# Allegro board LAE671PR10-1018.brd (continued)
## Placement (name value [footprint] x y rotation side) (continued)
PQ129  -  [DMN66D0LDW-7_SOT363-6]  52.66 18.61 90 bottom
PQ133  S TR AO7401 1P SC70-3  [SI1303DL-T1-E3_SOT323-3]  33.12 17.61 0 bottom
PQ134  -  [DMN66D0LDW-7_SOT363-6]  33.84 12.81 180 bottom
PQ135  S TR AO7401 1P SC70-3  [SI1303DL-T1-E3_SOT323-3]  46.81 19.43 0 bottom
PQ136  -  [DMN66D0LDW-7_SOT363-6]  49.28 19.35 0 bottom
PQ149  -  [DMN66D0LDW-7_SOT363-6]  177.45 11.8 90 bottom
PQ150  S TR AO7401 1P SC70-3  [SI1303DL-T1-E3_SOT323-3]  181.52 10.71 0 bottom
PQ151  -  [DMN66D0LDW-7_SOT363-6]  215.7 4.01 270 bottom
PQ153  -  [AON7405_DFN8-5]  193.28 7.72 270 bottom
PQ155  -  [AON7405_DFN8-5]  185.68 5.72 90 bottom
PQ156  -  [L2N7002WT1G_SC70-3]  191.68 3.86 0 bottom
PQ157  -  [L2N7002WT1G_SC70-3]  184.69 9.81 90 bottom
PQ158  S TR AO7401 1P SC70-3  [SI1303DL-T1-E3_SOT323-3]  196.1 3.67 0 bottom
PQ199  -  [L2N7002WT1G_SC70-3]  26.13 24.81 270 bottom
PQ200  -  [L2N7002WT1G_SC70-3]  33.81 32.42 270 bottom
PQ201  -  [L2N7002WT1G_SC70-3]  212.74 14.17 90 bottom
PQ300  -  [L2N7002WT1G_SC70-3]  61.13 13.72 180 bottom
PQ302  -  [AON6992_DFN5X6D-8-7]  62.5 20.91 180 bottom
PQ304  -  [AON7405_DFN8-5]  83.22 12.63 90 bottom
PQ307  -  [AON6992_DFN5X6D-8-7]  75.02 20.95 270 bottom
PR100  499K_0402_1%  [R_0402]  34.41 17.86 180 top
PR101  300K_0402_1%  [R_0402]  36.31 9.25 180 bottom
PR102  1M_0603_1%  [R_0603]  84.57 9.09 180 bottom
PR103  499K_0402_1%  [R_0402]  39.87 6.69 180 top
PR106  49.9K_0402_1%  [R_0402]  33.19 18.93 90 top
PR107  100K_0402_1%  [R_0402]  36.87 5.04 0 top
PR108  0_0402_5%  [R0402_0OHM]  22.26 26.08 0 bottom
PR109  49.9K_0402_1%  [R_0402]  34.3 10.1 270 bottom
PR110  100K_0201_1%  [R_0201]  23.17 25.33 180 bottom
PR111  0_0402_5%  [R0402_0OHM]  23.18 24.58 180 bottom
PR112  100K_0201_1%  [R_0201]  27.21 24.6 0 bottom
PR114  0_0402_5%  [R0402_0OHM]  31.17 8.17 270 top
PR115  200K_0402_1%  [R_0402]  41.19 4.15 90 top
PR117  0_0402_5%  [R0402_0OHM]  29.79 31.52 0 bottom
PR118  100K_0402_1%  [R_0402]  46.65 6.26 270 top
PR119  100K_0201_1%  [R_0201]  31.45 30.82 270 bottom
PR120  0_0402_5%  [R0402_0OHM]  33.06 30.69 180 bottom
PR121  100K_0201_1%  [R_0201]  30.82 32.86 270 bottom
PR122  0_0402_5%  [R0402_0OHM]  31.21 21.04 0 top
PR123  0_0402_5%  [R0402_0OHM]  37.23 7.45 270 top
PR124  200K_0402_1%  [R_0402]  54.4 14.94 180 top
PR126  0_0402_5%  [R0402_0OHM]  216.69 13.46 180 bottom
PR127  200K_0402_1%  [R_0402]  60.5 9.94 270 bottom
PR128  499K_0402_1%  [R_0402]  43.93 18.88 270 top
PR129  300K_0402_1%  [R_0402]  50.99 8.57 270 top
PR130  499K_0402_1%  [R_0402]  46.01 8.72 270 top
PR132  0_0402_5%  [R0402_0OHM]  49.21 16.16 0 top
PR133  49.9K_0402_1%  [R_0402]  43.92 17.12 0 top
PR134  49.9K_0402_1%  [R_0402]  45.76 6.43 270 top
PR135  0_0402_5%  [R0402_0OHM]  42.97 5.16 270 top
PR136  0_0402_5%  [R0402_0OHM]  48.71 5.29 90 top
PR137  0_0402_5%  [R0402_0OHM]  213.11 15.91 0 bottom
PR138  0_0402_5%  [R0402_0OHM]  51.68 15.86 0 top
PR139  200K_0402_1%  [R_0402]  44.74 2.39 90 top
PR140  100K_0201_1%  [R_0201]  215.99 14.2 0 bottom
PR141  100K_0201_1%  [R_0201]  211.74 14.05 180 bottom
PR142  200K_0402_1%  [R_0402]  54.4 15.86 180 top
PR143  200K_0402_1%  [R_0402]  61.41 9.99 0 bottom
PR144  0_0402_5%  [R0402_0OHM]  49.6 5.29 90 top
PR145  0_0402_5%  [R0402_0OHM]  43.85 4.91 0 top
PR148  1M_0402_1%  [R_0402]  47.11 3.31 270 top
PR149  300K_0402_5%  [R_0402]  38.01 1.99 0 top
PR150  10K_0402_1%  [R_0402]  50.97 3.08 270 top
PR151  0_0402_5%  [R0402_0OHM]  51.98 3.59 270 top
PR152  100_0402_1%  [R_0402]  97.63 13.89 270 top
PR153  300K_0402_5%  [R_0402]  38.9 3.26 180 top
PR154  100_0402_1%  [R_0402]  99.52 13.89 270 top
PR155  100K_0402_1%  [R_0402]  49.14 1.99 180 top
PR156  0_0402_5%  [R0402_0OHM]  49.14 2.88 180 top
PR157  100_0402_1%  [R_0402]  100.43 13.9 270 top
PR158  100K_0402_1%  [R_0402]  59.09 6.26 0 top
PR166  1M_0402_1%  [R_0402]  32.25 19.26 180 top
PR170  0_0402_5%  [R0402_0OHM]  63.21 9.1 90 bottom
PR171  200K_0402_1%  [R_0402]  68.57 9.96 270 bottom
PR172  1M_0402_1%  [R_0402]  49.19 14.38 0 top
PR173  200K_0402_1%  [R_0402]  67.65 9.99 270 bottom
PR174  200K_0402_1%  [R_0402]  51.55 19.7 270 bottom
PR175  200K_0402_1%  [R_0402]  52.69 20.35 0 top
PR176  1M_0402_1%  [R_0402]  38.11 6.53 90 top
PR177  1M_0402_1%  [R_0402]  47.82 5.29 90 top
PR178  1M_0402_1%  [R_0402]  32.04 8.54 90 top
PR179  1M_0402_1%  [R_0402]  42.08 4.27 90 top
PR192  0_0402_5%  [R0402_0OHM]  53.61 16.77 180 top
PR195  0_0402_5%  [R0402_0OHM]  64.99 9.99 270 bottom
PR196  0_0402_5%  [R0402_0OHM]  66.79 9.99 180 bottom
PR200  0_0402_5%  [R0402_0OHM]  64.1 9.07 90 bottom
PR201  0_0402_5%  [R0402_0OHM]  51.7 14.08 0 top
PR202  0_0402_5%  [R0402_0OHM]  52.69 17.66 0 top
PR203  0_0402_5%  [R_0402]  51.7 14.97 0 top
PR204  0_0402_5%  [R_0402]  61.41 9.07 0 bottom
PR205  0_0402_5%  [R_0402]  65.88 9.07 0 bottom
PR206  0_0402_5%  [R0402_0OHM]  54.47 16.77 90 top
PR207  0_0402_5%  [R0402_0OHM]  54.47 18.55 90 top
PR208  0_0402_5%  [R0402_0OHM]  53.61 19.44 180 top
PR209  0_0402_5%  [R0402_0OHM]  51.7 19.44 270 top
PR213  300K_0402_1%  [R_0402]  32.6 14.61 90 top
PR214  300K_0402_1%  [R_0402]  33.49 15.53 270 top
PR215  200K_0402_1%  [R_0402]  30.86 11.79 90 bottom
PR217  0_0402_5%  [R0402_0OHM]  31.66 18.07 270 top
PR218  1M_0402_1%  [R_0402]  39.54 20.17 90 top
PR219  1M_0402_1%  [R_0402]  42.16 18.89 270 top
PR220  300K_0402_1%  [R_0402]  44.82 18.9 270 top
PR221  300K_0402_1%  [R_0402]  45.7 18.22 270 top
PR222  200K_0402_1%  [R_0402]  49.27 19.26 0 top
PR224  0_0402_5%  [R0402_0OHM]  49.29 18.36 0 top
PR228  1M_0402_1%  [R_0402]  32.55 17.15 90 top
PR229  1M_0402_1%  [R_0402]  50.2 17.48 180 top
PR230  0_0402_5%  [R0402_0OHM]  53.61 18.57 180 top
PR259  0_0402_5%  [R0402_0OHM]  216.69 2.89 270 bottom
PR260  49.9K_0402_1%  [R_0402]  194.3 4.46 180 bottom
PR261  499K_0402_1%  [R_0402]  184.29 6.97 90 bottom
PR262  300K_0402_1%  [R_0402]  198.01 2.71 270 bottom
PR263  499K_0402_1%  [R_0402]  195.52 6.23 270 bottom
PR264  300K_0402_1%  [R_0402]  196.39 6.23 270 bottom
PR266  1M_0402_1%  [R_0402]  214.59 1.72 0 bottom
PR267  0_0402_5%  [R0402_0OHM]  184.37 10.83 180 bottom
PR268  300K_0402_1%  [R_0402]  182.46 6.97 90 bottom
PR269  1M_0402_1%  [R_0402]  193.05 9.16 180 bottom
PR270  200K_0402_1%  [R_0402]  179.01 14.13 180 bottom
PR271  0_0402_5%  [R0402_0OHM]  194.3 1.81 180 bottom
PR272  1M_0402_1%  [R_0402]  180.3 11.94 90 bottom
PR273  100K_0402_1%  [R_0402]  179.67 9.4 90 bottom
PR274  49.9K_0402_1%  [R_0402]  183.43 8.77 0 bottom
PR275  1M_0402_1%  [R_0402]  193.39 3.58 0 bottom
PR276  200K_0402_1%  [R_0402]  216.68 4.68 270 bottom
PR277  1M_0402_1%  [R_0402]  187.7 8.97 90 bottom
PR278  0_0402_5%  [R0402_0OHM]  181.19 12.86 270 bottom
PR300  0.02_1206_1%  [R_1206_4P-D]  54.44 11.75 0 bottom
PR301  3.3_0402_1%  [R_0402]  63.79 18.75 270 top
PR302  3.3_0402_1%  [R_0402]  62.4 18.75 270 top
PR303  2_1206_5%  [R_1206]  56.05 17.15 0 top
PR304  .01_2512_1%  [R_2512]  74.93 13.51 0 bottom
PR305  442K_0402_1%  [R_0402]  58.12 10.87 90 top
PR306  2.2_0603_5%  [R_0603]  64.98 17.98 270 top
PR307  100K_0402_1%  [R_0402]  59.03 12.61 270 top
PR308  4.7_0402_5%  [R_0402]  67.21 16.24 90 top
PR309  2_1206_5%  [R_1206]  56.55 12.15 90 top
PR311  2.2_0603_5%  [R_0603]  69.36 13.41 270 bottom
PR313  0_0402_5%  [R0402_0OHM]  59.12 9.88 0 top
PR314  0_0402_5%  [R0402_0OHM]  59.09 8.96 0 top
PR315  75_0402_5%  [R_0402]  59.09 8.01 0 top
PR316  4.7_1206_5%  [R_1206]  65.81 26.26 180 top
PR317  4.7_1206_5%  [R_1206]  70.66 23.97 180 top
PR318  0_0402_5%  [R0402_0OHM]  70.02 8.97 0 bottom
PR319  100K_0402_1%  [R_0402]  60.73 12.39 0 bottom
PR320  154K_0402_1%  [R_0402]  60.74 11.49 0 bottom
PR321  0_0402_5%  [R0402_0OHM]  58.22 3.3 270 bottom
PR322  93.1K_0402_1%  [R_0402]  63.28 8.07 270 top
PR323  2.2_0402_1%  [R_0402]  70.14 10.2 180 top
PR324  2.2_0402_1%  [R_0402]  70.14 9.31 180 top
PR325  100K_0402_1%  [R_0402]  59.09 7.12 0 top
PR326  1M_0402_1%  [R_0402]  61.48 6.25 0 top
PR327  499_0402_1%  [R_0402]  65.09 8.06 270 top
PR328  1K_0402_1%  [R_0402]  15.36 4.15 180 top
PR329  0_0402_5%  [R0402_0OHM]  67.47 6.25 270 top
PR330  100_0402_1%  [R_0402]  69.24 7.52 0 top
PR331  100K_0402_1%  [R_0402]  63.18 2.37 180 bottom
PR332  0_0402_5%  [R0402_0OHM]  62.4 7.15 90 top
PR333  10K_0402_5%  [R_0402]  68.36 5.33 90 top
PR334  0_0402_5%  [R0402_0OHM]  59.06 10.81 0 top
PR335  1M_0402_1%  [R_0402]  61.71 3.37 0 bottom
PR336  100K_0402_1%  [R_0402]  60.49 2.45 0 bottom
PR340  1M_0402_1%  [R_0402]  60.86 16.8 0 bottom
PR341  0_0402_5%  [R0402_0OHM]  14.44 5.93 0 top
PR342  0_0402_5%  [R0402_0OHM]  29.07 19.46 270 bottom
PR343  0_0402_5%  [R0402_0OHM]  58.22 4.13 90 bottom
PR344  0_0402_5%  [R0402_0OHM]  68.53 6.7 270 bottom
PR345  0_0402_5%  [R0402_0OHM]  68.37 2.08 90 bottom
PR346  0_0402_5%  [R0402_0OHM]  68.37 4.73 270 bottom
PR500  0_0402_5%  [R_0402]  53.87 27.98 0 bottom
PR501  4.7_1206_5%  [R_1206]  52.5 31.73 180 top
PR502  100K_0402_5%  [R_0402]  47.77 27.7 180 bottom
PR503  0_0402_5%  [R0402_0OHM]  46.85 25.04 0 bottom
PR504  1K_0402_5%  [R_0402]  46.85 26.81 0 bottom
PR505  0_0402_5%  [R_0402]  42.18 27.32 90 top
PR506  0_0402_5%  [R_0402]  38.66 22.46 0 bottom
PR507  4.7_1206_5%  [R_1206]  41.71 31.33 180 top
PR508  499K_0402_1%  [R_0402]  36.87 23.18 90 bottom
PR509  499K_0402_1%  [R_0402]  35.99 23.91 270 bottom
PR510  0_0402_5%  [R0402_0OHM]  35.96 24.98 0 bottom
PR511  1K_0402_5%  [R_0402]  35.96 26.84 0 bottom
PR512  0_0603_5%  [R0603_0OHM]  38.9 33.48 0 top
PR600  100K_0402_5%  [R_0402]  113.45 3.74 180 bottom
PR601  100K_0402_5%  [R_0402]  113.45 2.72 180 bottom
PR602  4.7_0603_5%  [R_0603]  124.68 2.75 0 bottom
PR603  100K_0402_1%  [R_0402]  116.3 2.35 90 bottom
PR604  0_0402_5%  [R_0402]  115.19 1.74 180 bottom
PR605  100K_0402_1%  [R_0402]  118.06 3.29 270 bottom
PR606  0_0402_5%  [R0402_0OHM]  114.27 2.74 0 bottom
PR607  0_0402_5%  [R0402_0OHM]  113.48 9.93 270 bottom
PR608  1M_0402_1%  [R_0402]  114.36 9.03 90 bottom
PR609  0_0402_5%  [R0402_0OHM]  113.47 10.84 0 bottom
PR610  1M_0402_1%  [R_0402]  115.26 10.8 90 bottom
PR611  0_0402_5%  [R_0402]  117.93 11.67 180 bottom
PR612  0_0603_5%  [R_0603]  122.34 2.75 0 bottom
PR700  4.7_1206_5%  [R_1206]  140.57 4.66 180 top
PR701  0_0402_5%  [R_0402]  135.79 2.41 0 bottom
PR702  14K_0402_1%  [R_0402]  136.85 11.41 180 bottom
PR703  0_0402_5%  [R0402_0OHM]  131.78 9.24 180 bottom
PR704  1M_0402_1%  [R_0402]  131.76 8.37 270 bottom
PR705  20K_0402_1%  [R_0402]  134.68 8.69 90 bottom
PR706  0_0402_5%  [R_0402]  132.88 9.62 270 bottom
PR707  0_0402_5%  [R0402_0OHM]  133.77 8.7 90 bottom
PR800  0_0402_5%  [R_0402]  163.92 59.12 180 bottom
PR801  0_0402_5%  [R0402_0OHM]  163.91 60 180 bottom
PR802  412K_0402_1%  [R_0402]  154.9 64.18 0 bottom
PR803  4.7_0603_5%  [R_0603]  153.33 62 270 bottom
PR804  324K_0402_1%  [R_0402]  156.76 64.17 270 bottom
PR805  100K_0402_5%  [R_0402]  153.91 64.09 180 bottom
PR806  0_0402_5%  [R0402_0OHM]  160.73 65.02 180 bottom
PR900  0_0402_5%  [R0402_0OHM]  152.03 4.37 270 bottom
PR901  0_0402_5%  [R_0402]  152.06 6.13 270 bottom
PR902  412K_0402_1%  [R_0402]  160.79 8.2 180 bottom
PR903  4.7_0805_5%  [R_0805]  156.76 12.4 90 bottom
PR904  324K_0402_1%  [R_0402]  159.87 6.44 0 bottom
PR905  100K_0402_5%  [R_0402]  158.29 8.83 90 bottom
PR906  0_0402_5%  [R0402_0OHM]  159.86 5.06 0 bottom
PR1000  8.25K_0402_1%  [R_0402]  35.52 42.04 90 top
PR1001  1_0402_5%  [R_0402]  35.3 48.72 0 bottom
PR1002  0_0402_5%  [R0402_0OHM]  38.27 49.69 180 bottom
PR1003  45.3_0402_1%  [R_0402]  33.56 46.08 0 top
PR1004  100_0402_1%  [R_0402]  33.57 47.71 0 top
PR1005  10_0402_1%  [R_0402]  35.31 47.84 0 top
PR1006  93.1K_0402_1%  [R_0402]  37.4 42.04 90 bottom
PR1007  0_0402_5%  [R0402_0OHM]  35.31 46.96 0 top
PR1008  49.9_0402_1%  [R_0402]  35.32 46.08 0 top
PR1009  100_0402_1%  [R_0402]  37.72 47.46 270 bottom
PR1010  27.4K_0402_1%  [R_0402]  37.4 41.21 0 top
PR1011  10.2K_0402_1%  [R_0402]  38.29 42.06 90 top
PR1012  1.91K_0402_1%  [R_0402]  35.32 44.3 0 top
PR1013  165K_0402_1%  [R_0402]  37.04 52.82 90 top
PR1014  34K_0402_1%  [R_0402]  36.19 52.65 180 top
PR1015  150K_0402_1%  [R_0402]  36.19 51.76 180 top
PR1016  110K_0402_1%  [R_0402]  36.19 50.87 180 top
PR1017  0_0402_5%  [R0402_0OHM]  35.32 45.19 0 top
PR1018  3.6K_0402_1%  [R_0402]  39.21 42.04 90 bottom
PR1019  2K_0402_1%  [R_0402]  40.98 40.29 90 top
PR1020  0_0402_5%  [R0402_0OHM]  34.56 42.07 90 top
PR1021  665_0402_1%  [R_0402]  39.68 52.83 90 top
PR1022  1K_0402_1%  [R_0402]  40.1 40.29 90 top
PR1023  34K_0402_1%  [R_0402]  37.95 52.81 90 top
PR1024  1K_0402_1%  [R_0402]  38.83 54.57 90 top
PR1025  11K_0402_1%  [R_0402]  36.16 54.57 90 top
PR1026  2.61K_0402_1%  [R_0402]  38.8 57.26 270 top
PR1027  1.91K_0402_1%  [R_0402]  39.2 40.25 90 top
PR1028  316_0402_1%  [R_0402]  42.64 55.53 270 top
PR1029  1.69K_0402_1%  [R_0402]  41.77 53.75 270 top
PR1030  2.61K_0402_1%  [R_0402]  42.13 42.98 270 bottom
PR1031  1K_0402_1%  [R_0402]  43.91 42.12 180 bottom
PR1032  2.43K_0402_1%  [R_0402]  44.59 54.69 0 top
PR1033  2K_0402_1%  [R_0402]  41.78 54.63 180 top
PR1034  11K_0402_1%  [R_0402]  40.4 42.96 270 bottom
PR1035  115K_0402_1%  [R_0402]  44.62 52.89 90 top
PR1036  360_0402_1%  [R_0402]  42.13 42.07 90 top
PR1037  383_0402_1%  [R_0402]  46.08 49.53 0 bottom
PR1038  11K_0402_1%  [R_0402]  48.8 48.93 0 bottom
PR1039  1K_0402_1%  [R_0402]  47.89 50.4 270 bottom
PR1040  5.49K_0402_1%  [R_0402]  48.78 50.76 0 bottom
PR1041  10.2K_0402_1%  [R_0402]  48.38 44.81 180 bottom
PR1042  316_0402_1%  [R_0402]  46.06 48.44 0 bottom
PR1043  100K_0402_1%  [R_0402]  46.43 44.81 270 bottom
PR1044  27.4K_0402_1%  [R_0402]  48.38 43.94 180 bottom
PR1045  2K_0402_1%  [R_0402]  46.05 47.55 0 top
PR1046  1.54K_0402_1%  [R_0402]  46.06 47.56 0 bottom
PR1047  2.26K_0402_1%  [R_0402]  48.68 45.93 0 bottom
PR1048  0_0402_5%  [R_0402]  44.77 42.96 270 bottom
PR1049  0_0402_5%  [R0402_0OHM]  45.53 52.89 90 top
PR1050  0_0402_5%  [R_0402]  46.52 52.89 90 top
PR1100  0_0402_5%  [R_0402]  61.54 60.49 270 bottom
PR1101  10_1206_5%  [R_1206]  70.41 60.22 90 top
PR1102  0_0402_5%  [R_0402]  61.18 49.33 0 top
PR1103  0_0402_5%  [R_0402]  61.19 48.44 0 top
PR1104  100K_0402_1%  [R_0402]  48.79 50.36 270 top
PR1105  3.65K_0603_1%  [R_0603]  49.82 49.6 90 top
PR1106  2.2_0402_1%  [R_0402]  48.73 51.57 180 top
PR1107  100K_0402_1%  [R_0402]  50.61 52.36 180 top
PR1108  0_0402_5%  [R_0402]  61.16 50.63 0 top
PR1109  0_0402_5%  [R_0402]  61.23 50.83 0 bottom
PR1110  10_1206_5%  [R_1206]  68.72 49.38 90 top
PR1111  0_0402_5%  [R_0402]  61.15 51.54 0 top
PR1112  3.65K_0603_1%  [R_0603]  41.61 44.28 180 bottom
PR1113  100K_0402_1%  [R_0402]  48.35 52.92 180 top
PR1114  3.65K_0603_1%  [R_0603]  49.44 53.45 0 top
PR1115  2.2_0402_1%  [R_0402]  46.96 51.6 180 top
PR1116  100K_0402_1%  [R_0402]  47.88 50.38 270 top
PR1117  100K_0402_1%  [R_0402]  42.61 44.33 0 bottom
PR1118  2.2_0402_1%  [R_0402]  46.87 42.02 90 bottom
PR1119  100K_0402_1%  [R_0402]  45.85 42.02 90 bottom
PR1150  0_0402_5%  [R_0402]  62.87 42.59 270 bottom
PR1151  4.7_1206_5%  [R_1206]  72.35 42.48 270 top
PR1152  3.65K_0603_1%  [R_0603]  51.35 42.18 270 top
PR1153  100K_0402_1%  [R_0402]  45.65 42.04 90 top
PR1154  2.2_0402_1%  [R_0402]  44.52 41.1 180 top
PR1155  100K_0402_1%  [R_0402]  44.76 42.05 90 top
PR1156  2.2_0603_1%  [R_0603]  54.59 45.04 180 bottom
PR1157  4.7_1206_5%  [R_1206]  54.61 56.82 270 top
PR1158  3.65K_0603_1%  [R_0603]  41.19 56.73 180 top
PR1159  0_0402_5%  [R0402_0OHM]  35.22 55.53 270 top
PR1400  0_0402_5%  [R0402_0OHM]  163.17 50.99 90 bottom
PR1401  0_0402_5%  [R0402_0OHM]  164.97 50.11 180 bottom
PR1402  0_0402_5%  [R_0402]  164.06 51.02 0 bottom
PR1403  4.7_0603_5%  [R_0603]  156.57 54.69 180 bottom
PR1404  10K_0402_1%  [R_0402]  166.57 58.25 180 bottom
PR1405  10K_0402_1%  [R_0402]  167.5 57.38 180 bottom
PR1406  10K_0402_1%  [R_0402]  165.65 59.15 0 bottom
PR1407  10K_0402_1%  [R_0402]  165.72 56.46 90 bottom
PR1408  100_0402_1%  [R_0402]  160.82 58.25 0 bottom
PR1409  0_0402_5%  [R0402_0OHM]  162.6 58.25 0 bottom
PR1411  0_0402_5%  [R_0402]  158.53 66.02 90 bottom
PR1412  130K_0402_1%  [R_0402]  162.56 66.03 90 bottom
PR1413  0_0402_5%  [R_0402]  161.67 66.95 270 bottom
PR1414  10K_0402_1%  [R_0402]  161.91 74.03 180 bottom
PR1415  10K_0402_1%  [R_0402]  161.94 71.18 180 bottom
PR1416  4.7_0603_5%  [R_0603]  154.15 72.91 90 bottom
PR1417  10K_0402_1%  [R_0402]  164.37 71.24 270 bottom
PR1418  10K_0402_1%  [R_0402]  163.4 71.24 270 bottom
PR1419  0_0402_5%  [R_0402]  161.91 72.24 180 bottom
PR1420  0_0402_5%  [R_0402]  161.91 73.16 180 bottom
PR1421  0_0402_5%  [R0402_0OHM]  155.21 73.94 270 bottom
PR1422  100K_0402_1%  [R_0402]  156.34 73.99 0 bottom
PR1423  10K_0402_1%  [R_0402]  162.29 51 90 bottom
PR1424  10K_0402_1%  [R_0402]  159.49 66.03 90 bottom
PR1500  0_0402_5%  [R_0402]  58.45 37.52 270 bottom
PR1501  0_0402_5%  [R_0402]  57.57 37.54 270 bottom
PR1502  0_0402_5%  [R_0402]  55.79 36.58 90 bottom
PR1503  10K_0402_1%  [R_0402]  58.46 29.8 90 bottom
PR1504  10K_0402_1%  [R_0402]  57.57 29.8 90 bottom
PR1505  4.7_0603_5%  [R_0603]  63.98 32.93 180 top
PR1506  100_0402_1%  [R_0402]  62.2 29.79 90 bottom
PR1507  10K_0402_1%  [R_0402]  58.46 30.72 90 top
PR1508  10K_0402_1%  [R_0402]  57.57 30.72 90 top
PR1509  0_0402_5%  [R_0402]  61.33 30.7 270 bottom
PR1510  0_0402_5%  [R_0402]  60.44 30.69 270 bottom
PR1511  0_0402_5%  [R_0402]  68.73 37.73 270 bottom
PR1512  0_0402_5%  [R_0402]  67.85 37.71 270 bottom
PR1513  0_0402_5%  [R_0402]  66.1 36.8 90 bottom
PR1514  10K_0402_1%  [R_0402]  65.95 29.36 0 bottom
PR1515  10K_0402_1%  [R_0402]  65.07 29.35 90 bottom
PR1516  4.7_0603_5%  [R_0603]  73.38 33 90 top
PR1517  10K_0402_1%  [R_0402]  67.79 30.27 270 bottom
PR1518  10K_0402_1%  [R_0402]  66.88 30.46 180 bottom
PR1519  100_0402_1%  [R_0402]  72.8 30.29 270 bottom
PR1520  0_0402_5%  [R_0402]  70.41 29.54 90 top
PR1521  0_0402_5%  [R_0402]  69.51 29.54 90 top
PR1522  10K_0402_1%  [R_0402]  59.32 37.55 270 bottom
PR1523  10K_0402_1%  [R_0402]  69.75 37.73 270 bottom
PR1524  0_0402_5%  [R_0402]  64.21 29.34 180 bottom
PR1525  100K_0402_1%  [R_0402]  63.29 30.24 0 bottom
PR1526  0_0402_5%  [R_0402]  60.35 31.95 90 top
PR1527  0_0402_5%  [R_0402]  69.55 30.28 270 bottom
PR1528  0_0805_5%  [R_0805]  62.82 36.91 0 bottom
PR1529  0_0805_5%  [R_0805]  75.06 36.06 90 bottom
PR1530  100K_0402_5%  [R_0402]  70.42 29.36 90 bottom
PR1531  5.1K_0402_1%  [R_0402]  71.5 29.34 90 bottom
PT100  PAD~D  [TPC12]  54.04 10.13 90 bottom
PT101  PAD~D  [TPC12]  33.97 21.81 270 bottom
PT102  PAD~D  [TPC12]  25.66 27.24 180 top
PT103  PAD~D  [TPC12]  202.15 2.89 0 bottom
PT104  PAD~D  [TPC12]  59.86 2.47 180 bottom
PT105  PAD~D  [TPC12]  47.93 1.63 180 bottom
PT106  PAD~D  [TPC12]  13.81 24.17 180 bottom
PT107  PAD~D  [TPC12]  15.94 24.16 180 bottom
PT108  PAD~D  [TPC12]  202.01 4.35 180 bottom
PT109  PAD~D  [TPC12]  201.53 1.76 180 bottom
PU101  -  [RT9069-33GB_SOT23-5]  36.87 2.54 90 bottom
PU300  -  [ISL88738HRTZ-T_TQFN32_4X4]  66.07 10.61 180 top
PU301  -  [MC74VHC1G08DFT2G_SC70-5]  66.07 4.17 0 bottom
PU500  -  [SY8286BRAC_QFN20_3X3]  52.29 27.68 180 bottom
PU501  SY8288CRAC_QFN20_3X3  [SY8286CRAC_QFN20_3X3]  41.34 26.38 180 bottom
PU600  -  [SY8210AQVC_QFN19_4X3]  116.57 7.68 270 bottom
PU700  -  [SY8286RAC_QFN20_3X3]  135.7 4.27 90 bottom
PU800  TLV62150ARGTR_QFN16_3X3  [TLV62150RGTR_QFN16_3X3-S]  158.24 61.35 90 bottom
PU900  TLV62150ARGTR_QFN16_3X3  [TLV62150RGTR_QFN16_3X3-S]  156.18 7.42 0 bottom
PU1000  -  [ISL95829AHRTZ-T_TQFN48_6X6]  38.97 44.85 90 top
PU1100  AOZ5049QI_QFN24_5X3P5  [AOZ5049QI_QFN24_5X3P5-S]  62.84 59.3 90 bottom
PU1101  AOZ5049QI_QFN24_5X3P5  [AOZ5049QI_QFN24_5X3P5-S]  63.41 49.7 90 bottom
PU1150  AOZ5049QI_QFN24_5X3P5  [AOZ5049QI_QFN24_5X3P5-S]  64.2 41.23 90 bottom
PU1151  -  [AOZ5029QI_QFN24_5X3P5]  55.84 47 180 bottom
PU1400  TPS62134ARGT_QFN16_3X3  [TPS62134ARGT_QFN16_3X3-S]  161.2 54.57 0 bottom
PU1401  TPS62134DRGT_QFN16_3X3  [TPS62134BRGT_QFN16_3X3-S]  156.52 70.38 0 bottom
PU1500  TPS62134CRGT_QFN16_3X3  [TPS62134CRGT_QFN16_3X3-S]  61.15 34.35 180 bottom
PU1501  TPS62134CRGT_QFN16_3X3  [TPS62134CRGT_QFN16_3X3-S]  71.87 34.14 180 bottom
Q4  -  [L2N7002WT1G_SC-70-3]  7.07 15.55 90 top
QC1  -  [DMN66D0LDW-7_SOT363-6]  144.1 54.26 90 bottom
QC2  -  [DMN66D0LDW-7_SOT363-6]  277.85 14.7 270 bottom
QE2  -  [DMN66D0LDW-7_SOT363-6]  33.25 27.78 270 bottom
QE10  -  [L2N7002WT1G_SC-70-3]  8.93 9.8 180 top
QE11  -  [DMN65D8LDW-7_SOT363-6]  29.26 2.18 180 bottom
QE12  LMBT3904WT1G SC70-3  [MMBT3904WT1G_SC70-3]  122.85 55.71 270 top
QE13  -  [L2N7002WT1G_SC-70-3]  12.93 26.75 90 bottom
QE14  LMBT3904WT1G SC70-3  [MMBT3904WT1G_SC70-3]  133.77 10.5 180 top
QE15  LMBT3904WT1G SC70-3  [MMBT3904WT1G_SC70-3]  161.41 11.64 180 bottom
QE16  LMBT3904WT1G SC70-3  [MMBT3904WT1G_SC70-3]  16.23 26.12 270 bottom
QE19  LMBT3904WT1G SC70-3  [MMBT3904WT1G_SC70-3]  287.13 41.84 90 bottom
QE20  LMBT3904WT1G SC70-3  [MMBT3904WT1G_SC70-3]  70.05 2.4 180 bottom
QE21  LMBT3904WT1G SC70-3  [MMBT3904WT1G_SC70-3]  169.39 71.47 0 top
QE22  LMBT3904WT1G SC70-3  [MMBT3904WT1G_SC70-3]  143.74 74.12 180 top
QE23  -  [L2N7002WT1G_SC-70-3]  268.1 58.01 180 top
QH1  -  [DMN66D0LDW-7_SOT363-6]  8.49 23.56 90 bottom
QH2  -  [DMN66D0LDW-7_SOT363-6]  12.88 21.36 180 bottom
QR1  -  [L2N7002WT1G_SC-70-3]  294.23 30.44 90 bottom
QZ1  -  [DMG2301U-7_SOT23-3]  287.01 26.53 90 bottom
R1  0_0402_1%  [R0402_0OHM]  152.33 40.5 180 top
R2  0_0603_5%  [R0603_0OHM]  99.7 67.81 180 top
R3  0_0201_5%  [R_0201]  126.53 51.39 270 top
R4  0_0201_5%  [R_0201]  141.26 54.06 0 top
R6  0_0603_5%  [R0603_0OHM]  279.78 33.05 0 bottom
R13  220K_0402_5%~D  [R_0402]  43.14 51.65 0 bottom
R14  0_0201_5%  [R0201_0OHM]  39.28 57.32 90 bottom
R15  0_0201_5%  [R0201_0OHM]  40.04 57.32 90 bottom
R16  4.7K_0402_5%  [R_0402]  56.24 68.03 270 bottom
R17  1K_0402_1%  [R_0402]  277.56 61.83 90 top
R18  0_0603_5%  [R0603_0OHM]  269.24 2.02 90 bottom
R19  0_0603_5%  [R_0603]  171.57 20.11 270 bottom
R22  10K_0201_5%  [R_0201]  174.12 9.74 0 bottom
R23  0_0402_5%~D  [R_0402]  286.17 55.43 180 bottom
R24  0_0402_5%~D  [R_0402]  285.23 45.68 180 top
R25  0_0402_5%~D  [R_0402]  285.23 44.79 180 top
R26  0_0402_5%~D  [R_0402]  285.23 43.9 180 top
R29  10K_0402_5%~D  [R_0402]  151.31 26.29 90 top
R30  0_0402_1%  [R0402_0OHM]  155.23 40.04 270 bottom
R31  0_0402_1%  [R0402_0OHM]  156.19 40.04 270 bottom
R32  10K_0402_5%~D  [R_0402]  150.41 27.22 270 top
R33  0_0402_5%~D  [R_0402]  153.27 26.95 180 top
R34  10K_0402_5%~D  [R_0402]  159.74 40.04 270 bottom
R35  0_0402_1%  [R0402_0OHM]  160.69 40.04 270 bottom
R36  10K_0402_5%~D  [R_0402]  254.78 12.31 90 bottom
R37  10K_0402_5%~D  [R_0402]  253.86 12.31 90 bottom
R38  10K_0402_5%~D  [R_0402]  254.99 4.38 90 bottom
R39  10K_0402_5%~D  [R_0402]  202.49 9.56 270 bottom
R40  10K_0402_5%~D  [R_0402]  199.61 8.85 270 bottom
R41  10K_0402_5%~D  [R_0402]  212.47 4.29 270 bottom
R42  0_0603_5%  [R_0603]  266.87 31.49 270 top
R44  100K_0201_5%  [R_0201]  277.55 24.08 180 top
R45  100K_0201_5%  [R_0201]  277.55 23 180 top
R46  0_0402_1%  [R0402_0OHM]  275.59 26.31 0 top
R47  0_0402_1%  [R0402_0OHM]  275.59 25.44 0 top
R48  1K_0402_5%  [R_0402]  263.56 21.42 90 top
R49  4.7K_0402_5%  [R_0402]  275.03 30.37 270 top
R50  0_0402_5%  [R_0402]  272.43 31.29 270 top
R51  22_0402_5%  [R_0402]  269.64 20.42 270 top
R53  20K_0402_5%  [R_0402]  263.56 24.09 270 top
R54  20K_0402_5%  [R_0402]  265.02 26.05 0 top
R55  0_0402_5%  [R_0402]  276.23 19.93 270 top
R56  0_0402_5%  [R_0402]  277.1 19.95 270 top
R57  4.7K_0402_5%  [R_0402]  275.96 21.67 180 top
R58  4.7K_0402_5%  [R_0402]  276.82 21.67 0 top
R62  2M_0201_5%  [R_0201]  275.6 27.03 0 top
R63  2M_0201_5%  [R_0201]  275.59 24.72 0 top
R67  820_0402_5%~D  [R_0402]  5.82 13.48 270 top
R68  820_0402_5%~D  [R_0402]  5.83 15.25 270 top
R69  820_0402_5%~D  [R_0402]  5.84 17.06 270 top
R70  820_0402_5%~D  [R_0402]  6.76 24.07 180 top
R71  820_0402_5%~D  [R_0402]  6.75 26.91 180 top
R73  0_0603_5%  [R0603_0OHM]  47.77 59.44 0 top
R76  100K_0402_5%~D  [R_0402]  50.8 63.9 90 top
R79  0_0603_5%  [R0603_0OHM]  146.87 32.38 270 top
R80  0_0603_5%  [R0603_0OHM]  225.19 10.96 0 top
R81  0_0402_5%  [R_0402]  152.26 25.43 270 top
R82  0_0402_1%  [R0402_0OHM]  151.21 22.72 90 top
R83  0_0603_5%  [R0603_0OHM]  146.86 34.68 90 top
R84  0_0603_5%  [R0603_0OHM]  225.12 7.79 0 top
R85  100K_0402_5%~D  [R_0402]  152.3 23.52 0 top
R86  100K_0402_5%~D  [R_0402]  219.8 8.04 180 top
R87  100K_0402_5%~D  [R_0402]  151.2 24.5 90 top
R88  100K_0402_5%~D  [R_0402]  218.89 9.94 0 top
R89  100K_0402_5%~D  [R_0402]  219.8 9.06 180 top
R90  0_0402_5%  [R_0402]  152.31 21.74 0 top
R91  0_0402_1%  [R0402_0OHM]  152.31 22.63 0 top
R92  0_0603_5%  [R0603_0OHM]  269.37 44.3 0 top
R93  0_0603_5%  [R0603_0OHM]  256.07 9.04 0 top
R94  0_0603_5%  [R0603_0OHM]  266.46 44.47 270 top
R95  0_0603_5%  [R0603_0OHM]  256.07 5.99 0 top
R96  100K_0402_5%~D  [R_0402]  268.17 50.55 270 top
R97  0_0603_5%  [R0603_0OHM]  47.86 55.96 180 bottom
R98  0_0603_5%  [R0603_0OHM]  286.17 28.4 180 bottom
R99  100K_0402_5%~D  [R_0402]  42.84 55.15 270 bottom
R100  100K_0402_5%  [R_0402]  290.84 28.64 270 bottom
R101  0_0603_5%  [R0603_0OHM]  137.35 70 90 top
R102  0_0603_5%  [R0603_0OHM]  150.42 13.5 90 bottom
R103  0_0603_5%  [R0603_0OHM]  122.85 41.13 0 top
R104  0_0603_5%  [R0603_0OHM]  125.77 70.82 0 top
R113  4.7K_0402_5%  [R_0402]  167.12 2.27 90 bottom
R114  4.7K_0402_5%  [R_0402]  167.12 4.94 270 bottom
R115  80.6_0402_1%~D  [R_0402]  32.3 23.5 90 top
R116  200K_0402_1%  [R_0402]  31.61 28.79 180 bottom
R117  100K_0402_5%~D  [R_0402]  176.7 9.84 180 bottom
R164  0_0402_5%  [R_0402]  22.84 54.32 270 top
R165  1M_0201_1%  [R_0201]  29.38 54.69 90 bottom
R166  100K_0201_5%  [R_0201]  23.17 54.67 0 bottom
R167  4.7K_0201_5%  [R_0201]  16.97 33.74 180 bottom
R168  4.7K_0201_5%  [R_0201]  16.97 33.1 180 bottom
R169  4.7K_0201_5%  [R_0201]  16.97 30.94 180 bottom
R170  4.7K_0201_5%  [R_0201]  4.98 33.27 270 bottom
R173  0_0201_5%  [R0201_0OHM]  22.48 35.9 0 top
R175  0_0201_5%  [R0201_0OHM]  22.86 28.28 0 top
R176  0_0201_5%  [R0201_0OHM]  21.63 29.88 270 bottom
R177  10K_0402_5%  [R_0402]  22.65 38.08 270 top
R178  0_0201_5%  [R0201_0OHM]  12.26 35.35 180 top
R179  10K_0402_5%  [R_0402]  23.53 38.06 270 top
R180  0_0402_1%  [R0402_0OHM]  13.27 34.45 0 top
R181  0_0201_5%  [R_0201]  18.89 26.31 270 top
R182  0_0402_1%  [R0402_0OHM]  13.27 35.34 0 top
R183  100K_0402_5%  [R_0402]  19.39 24.8 180 top
R184  15K_0402_1%  [R_0402]  21.76 37.17 90 top
R185  100K_0402_5%  [R_0402]  13.27 33.56 0 top
R186  100K_0402_5%  [R_0402]  16.8 35.97 270 top
R187  0_0201_5%  [R0201_0OHM]  16.4 32.47 270 bottom
R189  0_0201_5%  [R0201_0OHM]  17.08 32.47 270 bottom
R191  0_0201_5%  [R_0201]  11.6 32.98 0 top
R192  0_0201_5%  [R_0201]  11.86 32.24 0 top
R201  0_0201_5%  [R0201_0OHM]  35.7 38.46 270 top
R203  0_0201_5%  [R0201_0OHM]  35.94 30.94 0 top
R204  0_0201_5%  [R0201_0OHM]  34 30.88 270 bottom
R205  10K_0402_5%  [R_0402]  27.73 40.22 270 top
R206  0_0201_5%  [R0201_0OHM]  27.04 33.48 180 top
R207  10K_0402_5%  [R_0402]  26.84 40.22 270 top
R208  0_0402_1%  [R0402_0OHM]  25.82 36.68 0 top
R209  0_0201_5%  [R_0201]  30.52 27.93 270 top
R210  0_0402_1%  [R0402_0OHM]  25.82 37.57 0 top
R211  100K_0402_5%  [R_0402]  31.28 27.85 270 top
R212  100K_0402_5%  [R_0402]  28.61 39.66 270 top
R213  15K_0402_1%  [R_0402]  25.95 35.77 180 top
R214  100K_0402_5%  [R_0402]  29.55 39.66 270 top
R215  0_0201_5%  [R0201_0OHM]  26.16 33.61 0 bottom
R216  0_0201_5%  [R0201_0OHM]  26.16 32.98 0 bottom
R218  0_0201_5%  [R_0201]  24.89 35.01 0 top
R220  0_0201_5%  [R_0201]  24.89 34.37 0 top
R223  4.7K_0201_5%  [R_0201]  289.13 17.47 0 top
R224  4.7K_0201_5%  [R_0201]  289.12 16.86 0 top
R225  4.7K_0201_5%  [R_0201]  289.12 16.26 0 top
R226  4.7K_0201_5%  [R_0201]  288.52 17.48 90 top
R227  0_0201_5%  [R_0201]  288.23 20.8 90 bottom
R228  0_0201_5%  [R_0201]  287.67 20.8 90 bottom
R229  0_0201_5%  [R0201_0OHM]  279.83 14.03 180 bottom
R230  0_0201_5%  [R0201_0OHM]  280.46 15.56 90 bottom
R232  0_0201_5%  [R0201_0OHM]  294.54 15.62 0 bottom
R233  10K_0402_5%  [R_0402]  284.38 26.99 0 bottom
R234  0_0201_5%  [R0201_0OHM]  287.1 20.8 90 bottom
R235  10K_0402_5%  [R_0402]  282.64 26.99 0 bottom
R236  0_0201_5%  [R0201_0OHM]  284.78 21.44 270 bottom
R237  0_0201_5%  [R_0201]  292.34 17.8 90 bottom
R238  0_0201_5%  [R0201_0OHM]  285.35 21.44 270 bottom
R239  1M_0402_5%  [R_0402]  294.63 17.84 0 bottom
R240  15K_0402_1%  [R_0402]  281.34 17.1 270 bottom
R251  240_0402_1%  [R_0402]  280.87 17.47 270 top
R252  10K_0201_5%  [R_0201]  282.08 18.36 0 top
R253  0_0603_5%  [R0603_0OHM]  279.71 16.26 180 top
R255  0_0201_5%  [R0201_0OHM]  35.54 57.32 90 bottom
R256  0_0201_5%  [R0201_0OHM]  37.63 57.32 90 bottom
R257  0_0201_5%  [R0201_0OHM]  41.38 57.32 90 bottom
R258  0_0201_5%  [R0201_0OHM]  40.74 57.32 90 bottom
R259  0_0201_5%  [R0201_0OHM]  38.27 57.32 90 bottom
R260  0_0201_5%  [R0201_0OHM]  36.36 57.32 90 bottom
R261  0_0201_5%  [R0201_0OHM]  37 57.32 90 bottom
R262  0_0201_5%  [R0201_0OHM]  34.9 57.32 90 bottom
R264  0_0402_5%~D  [R_0402]  150.42 28.07 90 top
R265  0_0402_5%  [R_0402]  23.87 31.83 180 bottom
R266  0_0402_5%  [R_0402]  34.06 38.86 270 top
R267  0_0402_5%  [R_0402]  285.91 17.94 270 top
R268  0_0603_5%  [R0603_0OHM]  162.92 2.75 0 bottom
R269  240_0402_1%  [R_0402]  164.31 4.02 180 bottom
R270  100K_0402_5%~D  [R_0402]  164.2 9.86 180 bottom
R271  10K_0201_5%  [R_0201]  163.72 9.04 180 bottom
R272  0_0603_5%  [R0603_0OHM]  265.66 31.49 270 top
R274  47K_0201_5%  [R_0201]  75.53 3.23 270 top
R275  1/2W 0.0002 +-5%  [R_0805]  112.29 53.28 180 top
R276  1/2W 0.0002 +-5%  [R_0805]  110.59 53.28 180 top
R277  1/2W 0.0002 +-5%  [R_0805]  112.35 58.71 180 top
R278  1/2W 0.0002 +-5%  [R_0805]  110.64 58.71 180 top
R279  0_0402_5%  [R_0402]  108.06 51.92 0 top
R280  0_0402_5%  [R_0402]  107.74 60.46 90 top
R281  0438.500WR 0.5A 32V UL/CSA  [R_0603]  261.84 6.69 180 top
R282  0_0603_5%  [R_0603]  170.47 22.82 270 top
R283  0_0201_5%  [R_0201]  172.46 21.91 90 top
R284  0_0201_5%  [R_0201]  174.4 21.91 90 top
R285  0_0201_5%  [R_0201]  173.09 21.91 90 top
R286  0_0201_5%  [R_0201]  173.83 21.91 90 top
R288  300_0402_5%  [R_0402]  287.03 56.23 0 top
R5744  100K_0402_1%  [R_0402]  24.77 32.44 0 top
R5745  100K_0201_5%  [R_0201]  36.56 31.72 180 top
R5746  0_0402_1%  [R0402_0OHM]  23.87 33.59 180 bottom
R5747  0_0402_5%  [R_0402]  19.69 33.36 0 bottom
R5748  1M_0402_5%  [R_0402]  19.9 37.17 0 top
R5749  1M_0402_5%  [R_0402]  20.74 28.2 90 bottom
R5750  1M_0402_5%  [R_0402]  21.38 35.85 270 top
R5751  1M_0402_5%  [R_0402]  22.57 35.14 0 top
R5752  10K_0402_1%  [R_0402]  12.45 34.45 180 top
R5753  0_0201_5%  [R_0201]  17.31 23.32 180 top
R5754  0_0201_5%  [R_0201]  12.96 30.44 0 top
R5755  0_0201_5%  [R_0201]  12.96 29.42 0 top
R5756  100K_0402_1%  [R_0402]  11.52 36.2 0 top
R5757  100K_0201_5%  [R_0201]  17.26 23.96 180 top
R5758  0_0402_1%  [R0402_0OHM]  24.8 33.52 270 bottom
R5759  0_0402_5%  [R_0402]  30.3 37.8 180 bottom
R5760  1M_0402_5%  [R_0402]  32.17 27.59 270 top
R5761  1M_0402_5%  [R_0402]  34.98 37.94 90 top
R5762  10K_0402_1%  [R_0402]  25.69 33.61 180 top
R5763  0_0201_5%  [R_0201]  37.15 31.03 90 top
R5764  0_0201_5%  [R_0201]  26.16 34.25 0 bottom
R5765  0_0201_5%  [R_0201]  26.16 32.34 0 bottom
R5766  0_0402_1%  [R0402_0OHM]  287.72 17.97 270 top
R5767  0_0402_5%  [R_0402]  286.82 17.96 270 top
R5768  1M_0402_5%  [R_0402]  294.64 16.95 0 bottom
R5769  1M_0402_5%  [R_0402]  281.54 13.03 180 bottom
R5770  0_0201_5%  [R0201_0OHM]  294.54 16.21 0 bottom
R5771  0_0402_5%  [R_0402]  282.28 13.94 0 bottom
R5772  0_0402_5%  [R_0402]  279.49 14.8 0 bottom
R5773  0_0402_5%  [R_0402]  280.54 13.94 0 bottom
R5774  0_0201_5%  [R0201_0OHM]  23.43 31.11 180 top
R5775  0_0201_5%  [R0201_0OHM]  23.44 30.54 180 top
R5776  0_0201_5%  [R0201_0OHM]  23.43 32.27 180 top
R5777  0_0201_5%  [R0201_0OHM]  23.43 31.71 180 top
R5778  0_0201_5%  [R_0201]  35.4 34.82 0 top
R5779  0_0201_5%  [R_0201]  35.37 33.22 0 top
R5780  0_0201_5%  [R_0201]  35.37 33.81 0 top
R5781  0_0201_5%  [R_0201]  35.4 35.4 0 top
R5782  3.3K_0402_0.5%  [R_0402]  35.52 36.14 0 top
R5783  100K_0201_5%  [R_0201]  37.15 34.86 180 top
R5784  100K_0201_5%  [R_0201]  37.13 33.21 180 top
R5785  100K_0201_5%  [R_0201]  37.14 33.81 180 top
R5786  0_0201_5%  [R_0201]  282.95 12.78 180 bottom
R5787  0_0201_5%  [R0201_0OHM]  285.01 20.13 0 bottom
R5788  0_0201_5%  [R0201_0OHM]  285.93 20.79 0 bottom
R5789  100K_0201_5%  [R_0201]  281.47 15.36 270 bottom
R5790  1K_0201_5%  [R_0201]  287.6 20.18 180 bottom
R5791  0_0201_5%  [R0201_0OHM]  289.07 22.54 0 bottom
R5792  10K_0402_1%  [R_0402]  287.28 22.38 0 bottom
R5793  100K_0402_1%  [R_0402]  288.9 23.24 90 bottom
R5794  0_0402_1%  [R0402_0OHM]  24.12 29.67 180 top
R5795  0_0402_1%  [R0402_0OHM]  35.52 32.47 0 top
R5796  0_0402_1%  [R0402_0OHM]  287.45 16.11 0 top
R5797  1K_0402_5%  [R_0402]  264.17 25.86 90 top
R5798  1K_0402_5%  [R_0402]  270.37 16.72 180 top
R5800  1K_0402_5%  [R_0402]  269.58 18.5 0 top
R5801  1K_0402_5%  [R_0402]  271.34 17.62 180 top
R5802  1K_0402_5%  [R_0402]  272.63 20.25 180 top
R5803  1K_0402_5%  [R_0402]  270.68 30.56 0 top
R5804  1K_0402_5%  [R_0402]  268.9 30.56 0 top
R5805  1K_0402_5%  [R_0402]  268.77 28.53 90 top
R5806  1K_0402_5%  [R_0402]  267.91 29.42 270 top
R5807  1K_0402_5%  [R_0402]  272.23 18.5 180 top
R5808  0_0402_5%  [R_0402]  265.09 27.9 0 top
R5809  0_0402_5%  [R_0402]  277.14 20.78 0 top
R5811  0_0402_5%  [R_0402]  276.32 20.78 180 top
R5812  1K_0402_5%  [R_0402]  273.93 29.12 180 top
R5814  100K_0402_5%  [R_0402]  280.71 19.13 0 bottom
R5815  100K_0402_5%  [R_0402]  280.71 20.15 0 bottom
R5816  0_0201_5%  [R_0201]  280.65 12.19 270 bottom
R5817  0_0201_5%  [R_0201]  280.54 10.98 0 bottom
R5818  0_0201_5%  [R_0201]  282.07 12.2 270 bottom
R5819  0_0201_5%  [R_0201]  281.23 12.17 270 bottom
R5820  0_0201_5%  [R_0201]  172.45 23.14 90 top
R5821  0_0201_5%  [R_0201]  173.08 23.14 90 top
R5823  0_0402_1%  [R0402_0OHM]  51.87 61.03 90 top
R5824  240_0402_1%  [R_0402]  280.94 34.28 180 bottom
R5825  10K_0201_5%  [R_0201]  281.88 36.66 90 bottom
R5826  0_0603_5%  [R_0603]  282.28 34.41 270 bottom
R5827  0_0402_5%~D  [R_0402]  30.39 5.94 90 bottom
R5833  0_0402_5%~D  [R_0402]  277.99 29.23 0 top
R5834  20K_0402_5%  [R_0402]  272.63 19.37 180 top
R5835  0_0402_5%  [R_0402]  278 28.22 0 top
R5836  22_0402_5%  [R_0402]  267.41 20.66 270 top
R5837  10K_0402_5%  [R_0402]  269.79 59.04 270 top
R5838  0_0603_5%  [R_0603]  162.96 16.77 0 bottom
R5839  20K_0402_5%  [R_0402]  267.41 18.02 90 top
RA1  0_0402_1%  [R0402_0OHM]  277.46 67.01 180 top
RA2  1K_0402_1%  [R_0402]  275.71 62.54 0 top
RA3  0_0402_1%  [R0402_0OHM]  279.49 62.57 180 top
RA4  1K_0402_1%  [R_0402]  275.71 61.02 0 top
RA5  22_0402_5%  [R_0402]  271.72 59.49 90 top
RA6  22_0402_5%  [R_0402]  272.79 59.49 90 top
RA7  1K_0402_5%  [R_0402]  273.93 61.04 0 top
RA8  100K_0201_5%  [R_0201]  272.57 66.12 0 top
RA9  2.2K_0402_5%  [R_0402]  269.88 61.64 0 bottom
RA10  2.2K_0402_5%  [R_0402]  269.88 62.53 0 bottom
RA11  100K_0402_1%~D  [R_0402]  273.47 56.32 0 bottom
RA12  1K_0201_5%  [R_0201]  272.57 66.71 0 top
RA13  200K_0402_1%  [R_0402]  274.39 55.33 180 bottom
RA14  33_0201_1%  [R_0201]  275.5 66.9 270 bottom
RA15  100K_0201_5%  [R_0201]  273.15 65.54 180 top
RA16  100K_0402_1%~D  [R_0402]  279.74 57.46 0 bottom
RA17  33_0402_5%  [R_0402]  269.34 63.49 180 bottom
RA18  33_0402_5%  [R_0402]  271.18 64.38 180 bottom
RA19  33_0402_5%  [R_0402]  271.17 65.28 180 bottom
RA20  33_0402_5%  [R_0402]  271.17 66.17 180 bottom
RA21  33_0402_5%  [R_0402]  271.17 67.06 180 bottom
RA22  0_0402_1%  [R0402_0OHM]  266.82 11.13 180 bottom
RA23  0_0402_5%  [R_0402]  275.74 15.66 0 top
RA24  100K_0402_5%  [R_0402]  273.95 15.75 90 top
RA25  0_0402_5%  [R_0402]  272.84 15.75 90 top
RA26  0_0402_5%  [R_0402]  271.93 15.74 90 top
RA27  0_0402_1%  [R0402_0OHM]  272.84 13.91 90 top
RA28  10K_0402_0.1%  [R_0402]  268.44 9.56 270 bottom
RA29  10K_0402_0.1%  [R_0402]  267.49 7.42 0 bottom
RA30  10K_0402_5%  [R_0402]  268.31 13.72 90 top
RA31  10K_0402_0.1%  [R_0402]  266.79 6.38 0 bottom
RA32  10K_0402_0.1%  [R_0402]  267.26 4.86 0 bottom
RA33  0_0402_1%  [R0402_0OHM]  271.38 13.91 90 top
RA34  10K_0402_0.1%  [R_0402]  268.01 3.59 0 top
RA35  39K +-0.1% 0402  [R_0402]  270.22 8.86 180 bottom
RA36  10K_0402_0.1%  [R_0402]  270.77 3.59 180 top
RA37  39K +-0.1% 0402  [R_0402]  270.18 7.42 180 bottom
RA38  10K_0402_5%  [R_0402]  267.43 13.72 90 top
RA39  39K +-0.1% 0402  [R_0402]  269.47 6.38 180 bottom
RA40  22.6K_0402_1%  [R_0402]  273.97 14.88 270 top
RA41  39K +-0.1% 0402  [R_0402]  269.93 4.86 180 bottom
RA42  39K +-0.1% 0402  [R_0402]  268.91 1.73 90 top
RA43  39K +-0.1% 0402  [R_0402]  269.86 1.73 90 top
RA44  0.2_0805_ 1%  [R_0805]  281.02 12.35 0 top
RA45  0.2_0805_ 1%  [R_0805]  281.91 7.66 0 top
RA46  10_0402_1%  [R_0402]  279.33 13.44 180 top
RA47  10_0402_1%  [R_0402]  280.48 8.97 0 top
RA48  10_0402_1%  [R_0402]  278.45 6.68 180 top
RA49  10_0402_1%  [R_0402]  278.95 3.73 180 top
RA50  0_0402_5%  [R_0402]  291.84 6.18 180 top
RA51  2.2K_0402_5%~D  [R_0402]  282.36 63.66 270 bottom
RA52  BLM15PX330SN1D_2P  [MURAT_BLM15PX330SN1D_2P]  283.25 62.78 90 bottom
RA53  5.6_0402_5%  [R_0402]  286.51 58.57 0 bottom
RA54  5.6_0402_5%  [R_0402]  284.78 60.34 0 bottom
RA55  BLM15PX330SN1D_2P  [MURAT_BLM15PX330SN1D_2P]  283.28 60.95 90 bottom
RA56  2.2K_0402_5%~D  [R_0402]  282.39 61.83 270 bottom
RA57  0_0402_1%  [R0402_0OHM]  284.76 57.68 0 bottom
RA58  0_0402_1%  [R0402_0OHM]  284.75 58.58 0 bottom
RA59  9.09K_0402_1%  [R_0402]  285.67 59.45 180 bottom
RA60  9.09K_0402_1%  [R_0402]  286.53 57.68 0 bottom
RA61  22_0402_5%  [R_0402]  273.83 58.66 90 top
RA62  0_0402_5%  [R_0402]  291.84 5.3 180 top
RA63  0_0402_1%  [R0402_0OHM]  290.07 6.47 90 top
RA64  0_0402_1%  [R0402_0OHM]  289.19 6.47 90 top
RA65  BLM18EG221TN1D_2P~D  [MURAT_BLM18EG221SN1D_2P]  125.7 49.89 180 top
RA66  10K_0402_5%  [R_0402]  274.87 14.87 90 top
RC1  2.2K_0402_5%  [R_0402]  134.91 68.54 0 top
RC2  100K_0402_5%  [R_0402]  131.73 60.54 0 top
RC3  2.2K_0402_5%  [R_0402]  134.91 67.65 0 top
RC4  100K_0402_5%  [R_0402]  133.51 61.43 270 top
RC5  2.2K_0402_5%  [R_0402]  141.12 60.54 0 top
RC6  100K_0402_5%  [R_0402]  134.4 61.43 270 top
RC7  2.2K_0402_5%  [R_0402]  141.12 61.43 0 top
RC8  24.9_0402_1%  [R_0402]  107.72 62.32 90 top
RC9  100_0402_1%  [R_0402]  130.47 64.22 90 top
RC10  200_0402_1%  [R_0402]  141.05 48.22 0 bottom
RC11  200_0402_1%  [R_0402]  124.99 44.54 270 top
RC12  80.6_0402_1%  [R_0402]  125.88 44.54 270 top
RC13  162_0402_1%  [R_0402]  126.77 44.54 270 top
RC16  8.2K_0402_5%  [R_0402]  135.5 38.82 90 bottom
RC17  10K_0402_5%  [R_0402]  144.02 56.56 0 bottom
RC18  1K_0402_5%  [R_0402]  141.14 58.12 0 top
RC19  15_0402_5%  [R_0402]  135.47 40.57 0 bottom
RC20  1K_0402_5%  [R_0402]  141.14 57.23 0 top
RC21  10K_0402_5%  [R_0402]  132.63 38.82 90 bottom
RC22  22_0402_5%  [R_0402]  137.25 39.73 270 bottom
RC23  1K_0402_5%  [R_0402]  141.12 56.44 0 bottom
RC24  10K_0402_1%  [R_0402]  133.64 38.82 90 bottom
RC25  1K_0402_5%  [R_0402]  141.12 57.32 0 bottom
RC26  2.2K_0402_5%  [R_0402]  141.12 59.65 0 top
RC27  4.7K_0402_5%  [R_0402]  141.12 55.57 0 bottom
RC28  33_0402_5%  [R_0402]  169.39 39.19 90 bottom
RC29  150K_0402_1%  [R_0402]  135.21 49.49 0 top
RC30  0_0402_1%  [R0402_0OHM]  166.26 25.18 270 bottom
RC31  0_0402_1%  [R0402_0OHM]  167.43 25.18 270 bottom
RC32  0_0402_1%  [R0402_0OHM]  169.2 25.15 180 bottom
RC33  0_0402_1%  [R0402_0OHM]  166.48 39 90 bottom
RC34  0_0402_1%  [R0402_0OHM]  165.15 38.98 90 bottom
RC35  0_0402_1%  [R0402_0OHM]  163.93 38.95 90 bottom
RC36  0_0402_1%  [R0402_0OHM]  163.01 39.86 270 bottom
RC37  0_0402_5%  [R_0402]  162.12 38.94 90 bottom
RC38  10K_0402_5%  [R_0402]  142.03 53.49 180 bottom
RC39  10K_0402_5%  [R_0402]  140.77 40.37 90 top
RC40  10K_0402_5%  [R_0402]  142.01 52.03 180 bottom
RC41  100K_0402_5%~D  [R_0402]  141.9 39.78 270 bottom
RC45  2.2K_0402_5%  [R_0402]  136.25 47.59 180 top
RC46  2.2K_0402_5%  [R_0402]  136.12 48.6 180 top
RC47  113_0402_1%  [R_0402]  136.12 54.65 0 top
RC48  0_0402_1%  [R0402_0OHM]  141.1 50.99 0 bottom
RC49  1K_0402_5%  [R_0402]  136.43 51.84 0 top
RC50  100_0402_1%  [R_0402]  135.17 62.44 90 top
RC52  0_0201_5%  [R_0201]  136.17 61.68 270 top
RC53  10K_0402_5%  [R_0402]  134.53 69.61 90 bottom
RC54  10K_0402_5%  [R_0402]  135.43 69.65 90 bottom
RC55  10K_0402_5%  [R_0402]  136.37 69.64 90 bottom
RC56  10K_0402_5%  [R_0402]  133.64 69.61 90 bottom
RC57  1K_0402_5%  [R_0402]  131.67 39.71 270 bottom
RC58  10K_0402_5%  [R_0402]  144.18 51.59 270 bottom
RC59  1M_0402_1%  [R_0402]  118.4 68.41 90 bottom
RC60  47_0402_5%  [R_0402]  114.72 70.24 90 bottom
RC61  47_0402_5%  [R_0402]  115.61 70.24 90 bottom
RC62  10K_0402_5%  [R_0402]  145.96 49.36 180 bottom
RC63  10K_0402_5%  [R_0402]  139.88 40.37 90 top
RC64  2.7K_0402_1%  [R_0402]  111.8 62.74 90 top
RC65  10K_0402_5%  [R_0402]  145.07 51.21 270 bottom
RC66  10M_0402_5%  [R_0402]  136.21 39.83 0 top
RC67  10K_0402_5%  [R_0402]  29.87 49.44 90 top
RC68  20K_0402_5%  [R_0402]  132.49 37.67 270 top
RC69  0_0402_1%  [R0402_0OHM]  136.2 38.9 0 top
RC70  10K_0402_5%  [R_0402]  145.96 48.47 180 bottom
RC71  20K_0402_5%  [R_0402]  149.21 38.82 180 bottom
RC73  1K_0402_5%  [R_0402]  131.26 40.44 90 top
RC74  10K_0402_5%  [R_0402]  139.01 40.96 180 top
RC76  100K_0402_5%  [R_0402]  147.6 50.86 270 top
RC77  10K_0402_5%  [R_0402]  146.66 49.11 180 top
RC78  1M_0402_5%  [R_0402]  133.38 37.67 270 top
RC79  1K_0402_5%  [R_0402]  100.19 72.98 180 bottom
RC80  8.2K_0402_5%  [R_0402]  138.09 40.07 0 top
RC81  10K_0402_5%  [R_0402]  140.68 40.72 0 bottom
RC82  10K_0402_5%  [R_0402]  130.35 41.36 270 top
RC83  10K_0402_5%  [R_0402]  126.61 41.87 0 top
RC85  1K_0402_5%  [R_0402]  95.48 67.1 0 top
RC86  60.4_0402_1%  [R_0402]  97.19 71.97 180 bottom
RC87  0_0402_1%  [R0402_0OHM]  139.1 65.62 90 top
RC88  10K_0402_5%  [R_0402]  137.33 66.5 270 top
RC89  1K_0402_5%  [R_0402]  138.22 66.5 270 top
RC90  0_0402_5%  [R_0402]  130.23 38.84 90 bottom
RC92  100K_0402_5%~D  [R_0402]  129.58 37.57 270 top
RC106  49.9_0402_1%  [R_0402]  128.55 44.54 270 top
RC107  49.9_0402_1%  [R_0402]  127.66 44.54 270 top
RC108  49.9_0402_1%  [R_0402]  99.08 61.22 180 top
RC109  49.9_0402_1%  [R_0402]  100.18 61.23 270 top
RC110  1K_0402_5%  [R_0402]  153.22 39.6 90 top
RC111  33_0402_5%  [R_0402]  128.47 38.84 90 bottom
RC112  33_0402_5%  [R_0402]  125.64 39.44 90 bottom
RC113  33_0402_5%  [R_0402]  127.37 38.84 90 bottom
RC114  100K_0402_5%~D  [R_0402]  141.06 52.41 0 top
RC115  0_0402_1%  [R0402_0OHM]  140.5 60.47 0 bottom
RC116  200_0402_1%  [R_0402]  132.92 56.35 180 top
RC117  0_0402_1%  [R0402_0OHM]  133.76 64.53 90 top
RC118  2.2K_0402_5%  [R_0402]  136.83 46.38 180 top
RC119  4.7K_0402_5%  [R_0402]  126.7 41.25 180 bottom
RC120  10K_0402_1%  [R_0402]  96.92 73.12 180 bottom
RC121  10K_0402_1%  [R_0402]  93.69 67.82 90 top
RC122  10K_0402_1%  [R_0402]  95.09 70.84 270 top
RC123  1K_0402_5%  [R_0402]  93.07 66.63 0 top
RC124  49.9_0402_1%  [R_0402]  103.35 63.42 270 top
RC125  1.5K_0402_5%  [R_0402]  132.75 69.6 90 bottom
RC126  100K_0402_5%  [R_0402]  98.2 69.99 90 bottom
RC150  100_0402_1%  [R_0402]  120.82 66.07 270 top
RC151  100_0402_1%  [R_0402]  121.69 65.16 90 top
RC152  0_0603_5%  [R0603_0OHM]  101.03 62.95 0 top
RC153  0_0603_5%  [R0603_0OHM]  125.36 65.72 90 top
RC154  56_0402_1%  [R_0402]  101.63 71.97 180 bottom
RC155  220_0402_5%  [R_0402]  100.86 70.12 90 bottom
RC156  100_0402_1%  [R_0402]  99.09 70.91 270 bottom
RC157  0_0402_1%  [R0402_0OHM]  99.98 70.12 90 bottom
RC158  100_0402_1%  [R_0402]  99.34 71.02 180 top
RC159  0_0402_1%  [R0402_0OHM]  99.33 70.13 180 top
RC160  100_0402_1%  [R_0402]  94.78 60.2 90 top
RC161  100_0402_1%  [R_0402]  94.19 61.05 90 bottom
RC162  0_0402_1%  [R0402_0OHM]  115.47 51.09 270 top
RC163  100_0402_1%  [R_0402]  122.84 51.14 270 top
RC164  100_0402_1%  [R_0402]  125.5 61.18 0 top
RC165  0_0201_5%  [R_0201]  123.72 50.25 90 top
RC166  100_0402_1%  [R_0402]  125.38 63.41 270 top
RC167  0_0603_5%  [R0603_0OHM]  134.47 52.28 180 top
RC168  0_0603_5%  [R0603_0OHM]  137.06 63.59 270 top
RC169  0_0603_5%  [R0603_0OHM]  141.56 58.82 180 bottom
RC170  0_0603_5%  [R0603_0OHM]  132.12 52.2 180 top
RC171  0_0603_5%  [R0603_0OHM]  132.12 70.29 270 top
RC172  0_0603_5%  [R0603_0OHM]  133.39 70.25 270 top
RC173  0_0603_5%  [R0603_0OHM]  130.65 69.7 270 top
RC174  0_0603_5%  [R0603_0OHM]  143.52 38.26 180 top
RC175  0_0603_5%  [R0603_0OHM]  128.44 66.76 270 top
RC176  0_0603_5%  [R0603_0OHM]  137.31 53.56 180 top
RC177  BLM18EG221TN1D_2P~D  [MURAT_BLM18EG221SN1D_2P]  142.6 55.2 180 top
RC178  0_0402_5%  [R_0402]  166.16 16.96 270 bottom
RC179  0_0402_1%  [R0402_0OHM]  163.5 15.72 0 bottom
RC181  2.2K_0201_5%  [R_0201]  285.37 54.69 0 bottom
RC182  2.2K_0201_5%  [R_0201]  286.46 40.1 270 bottom
RC183  4.7K_0402_5%  [R_0402]  50.46 53.6 90 bottom
RC184  4.7K_0402_5%  [R_0402]  51.35 53.6 90 bottom
RC217  51_0402_5%  [R_0402]  89.88 73.34 0 bottom
RC218  1K_0402_1%  [R_0402]  100.2 71.05 270 top
RC219  49.9_0402_1%  [R_0402]  101.78 71.01 270 bottom
RC220  499_0402_1%  [R_0402]  96.94 70.57 270 top
RC221  1K_0402_1%  [R_0402]  96.94 72.3 270 top
RC222  60.4_0402_1%  [R_0402]  101.11 69.28 180 top
RC223  0_0402_5%  [R_0402]  96.37 69.97 90 bottom
RC225  100K_0201_5%  [R_0201]  146.13 47.07 180 bottom
RC226  1K_0402_5%  [R_0402]  129.19 69.68 0 bottom
RC227  0_0201_5%  [R_0201]  92.41 70.57 180 bottom
RC228  0_0201_5%  [R_0201]  89.12 72.3 180 bottom
RC229  0_0201_5%  [R_0201]  92.41 71.46 180 bottom
RC230  51_0402_5%  [R_0402]  104.61 71.13 90 bottom
RC231  0_0201_5%  [R_0201]  92.41 72.35 180 bottom
RC232  0_0201_5%  [R_0201]  89.14 73.77 180 bottom
RC233  0_0201_5%  [R_0201]  92.41 71.65 180 top
RC234  0_0201_5%  [R_0201]  91.82 70.89 0 top
RC235  0_0201_5%  [R_0201]  92.41 70 180 top
RC236  0_0201_5%  [R_0201]  101.22 70.12 90 top
RC237  0_0201_5%  [R_0201]  87.27 72.3 0 bottom
RC238  0_0201_5%  [R_0201]  93.28 67.37 0 bottom
RC239  51_0402_5%  [R_0402]  93.12 72.35 0 bottom
RC240  51_0402_5%  [R_0402]  93.12 71.46 0 bottom
RC241  1K_0201_5%  [R_0201]  141.48 46.44 0 bottom
RC242  100_0402_1%  [R_0402]  94.03 70.57 180 bottom
RC243  1K_0201_5%  [R_0201]  144.34 47.07 0 bottom
RC244  51_0402_5%  [R_0402]  89.87 72.46 0 bottom
RC245  0_0201_5%  [R_0201]  106.1 70.72 0 bottom
RC246  0_0201_5%  [R_0201]  106.1 70.16 0 bottom
RC247  0_0201_5%  [R_0201]  42.52 66.21 90 top
RC248  0_0201_5%  [R_0201]  137.83 64.85 180 top
RC249  0_0402_5%  [R_0402]  130.96 69.68 0 bottom
RC250  1K_0402_5%  [R_0402]  44.87 66.36 90 top
RC251  0_0402_5%  [R_0402]  40.04 65.73 90 top
RC252  51_0402_5%  [R_0402]  93.12 69.87 0 top
RC253  1K_0402_1%  [R_0402]  55.86 72.41 180 top
RC254  51_0402_5%  [R_0402]  93.12 70.76 0 top
RC255  100_0402_1%  [R_0402]  94.03 71.65 180 top
RC256  1K_0402_1%  [R_0402]  55.86 73.36 180 top
RC257  51_0402_5%  [R_0402]  87.75 73.07 180 bottom
RC258  51_0402_5%  [R_0402]  93.64 68.08 90 bottom
RC366  15_0402_5%  [R_0402]  128.46 41.38 270 top
RC367  15_0402_5%  [R_0402]  139.71 43.42 270 top
RC368  15_0402_5%  [R_0402]  129.35 41.38 270 top
RC369  15_0402_5%  [R_0402]  138.83 43.29 270 top
RC370  0_0402_5%  [R_0402]  143.3 48.17 270 bottom
RC371  1K_0402_5%  [R_0402]  43.98 66.36 90 top
RC372  4.7K_0402_5%  [R_0402]  48.38 57.87 180 bottom
RC373  4.7K_0402_5%  [R_0402]  48.38 58.76 180 bottom
RC374  1M_0402_1%  [R_0402]  142.55 62.5 270 bottom
RC375  33_0201_1%  [R_0201]  117.67 68.28 180 bottom
RC376  33_0201_1%  [R_0201]  119.14 68.31 0 bottom
RC377  33_0201_1%  [R_0201]  141.82 61.68 180 bottom
RC378  33_0201_1%  [R_0201]  141.82 62.44 180 bottom
RC379  0_0402_1%  [R0402_0OHM]  141.26 41.66 90 bottom
RC381  10K_0402_5%  [R_0402]  129 40.72 180 bottom
RC382  0_0603_5%  [R0603_0OHM]  166.03 10.37 0 bottom
RC383  0_0402_1%  [R0402_0OHM]  112.69 13.93 270 bottom
RC384  0_0402_1%  [R0402_0OHM]  139.24 50.39 270 top
RC386  0_0402_1%  [R0402_0OHM]  134.53 39.71 270 bottom
RC387  0_0402_1%  [R0402_0OHM]  146.01 55.84 0 top
RC388  0_0402_1%  [R0402_0OHM]  146.14 57.36 0 top
RC389  0_0402_5%  [R_0402]  149.86 51.18 0 bottom
RC390  0_0402_5%  [R_0402]  130.27 34.13 90 top
RC391  0_0201_5%  [R_0201]  92.47 67.02 270 bottom
RC393  22_0402_5%  [R_0402]  273.29 31.29 270 top
RC394  22_0402_5%  [R_0402]  274.16 31.29 270 top
RC395  10K_0402_5%  [R_0402]  143.66 56.97 0 top
RC396  1K_0402_5%  [R_0402]  26.8 55.15 0 top
RD1  240_0402_1%  [R_0402]  82.19 17.76 180 top
RD2  240_0402_1%  [R_0402]  99.99 15.87 270 top
RD3  240_0402_1%  [R_0402]  82.19 19.67 180 top
RD4  240_0402_1%  [R_0402]  99.12 15.88 270 top
RD5  240_0402_1%  [R_0402]  117.97 18.63 180 top
RD6  240_0402_1%  [R_0402]  134.05 15.63 0 top
RD7  240_0402_1%  [R_0402]  117.97 19.51 180 top
RD8  240_0402_1%  [R_0402]  133.39 22.1 90 top
RD9  8.2K_0402_1%  [R_0402]  98.97 34.61 90 top
RD10  4.99_0402_1%~D  [R_0402]  99.87 36.37 180 top
RD11  8.2K_0402_1%  [R_0402]  99.86 35.53 270 top
RD12  24.9_0402_1%  [R_0402]  98.11 37.28 270 top
RD13  8.2K_0402_1%  [R_0402]  90.27 33 180 top
RD14  8.2K_0402_1%  [R_0402]  91.18 32.21 90 top
RD15  10_0402_1%~D  [R_0402]  89.34 34.87 270 top
RD16  10_0402_1%~D  [R_0402]  92.07 34.9 270 top
RD17  8.2K_0402_1%  [R_0402]  88.46 33.05 180 top
RD18  8.2K_0402_1%  [R_0402]  92.07 33.12 270 top
RD19  24.9_0402_1%  [R_0402]  87.55 33.96 0 top
RD20  24.9_0402_1%  [R_0402]  90.27 33.96 90 top
RD21  68_0201_1%  [R_0201]  96.65 15.98 270 top
RD22  68_0201_1%  [R_0201]  127.99 16.25 270 top
RD23  68_0201_1%  [R_0201]  96.06 15.98 270 top
RD24  68_0201_1%  [R_0201]  127.41 16.25 270 top
RD25  68_0201_1%  [R_0201]  92.69 15.98 270 top
RD26  68_0201_1%  [R_0201]  126.27 16.25 270 top
RD27  68_0201_1%  [R_0201]  95.48 15.98 270 top
RD28  68_0201_1%  [R_0201]  126.84 16.25 270 top
RD29  68_0201_1%  [R_0201]  92.11 15.98 270 top
